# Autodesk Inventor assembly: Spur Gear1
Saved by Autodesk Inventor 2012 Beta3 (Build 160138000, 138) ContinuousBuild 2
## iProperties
Created: 2011-01
Part Number: Spur Gear1
Document SubType Name: Assembly
Designer: Beta-8540w
Categories: <?xml version="1.0" encoding="UTF-16"?> <MemberInstance><Categories><FamilyTemplate/><ParamToTemplateMap><ParamToTemplate><ParamToTemplate CategoryParameter="//
ClientObjectVersion: 1
Author: Beta-8540w
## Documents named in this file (2)
- C:\Inventor 2012 Essentials\Assemblies\Chapter 8\Design Accelerators\Spur Gear c98-02.iam
- C:\Inventor 2012 Essentials\Assemblies\Chapter 8\Design Accelerators\Spur Gear c8-02.ipt
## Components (1 placed, 1 different names)
1. Spur Gear2:1
